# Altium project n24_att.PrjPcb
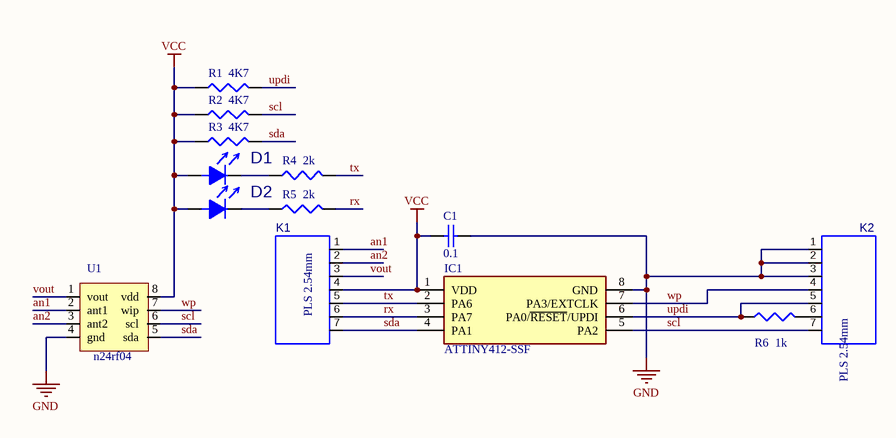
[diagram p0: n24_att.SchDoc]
1 sheet, 13 parts. Net scope: global (net labels, ports and power ports of the same name join across sheets).
Board file: n24_att.PcbDoc

## Sheet n24_att.SchDoc
size A4

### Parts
C1  value 0.1  [SM0805]  (hidden comment: cap0805)
D1  LIGHT_SM0805  [SM0805_diode]  (value not drawn)
D2  LIGHT_SM0805  [SM0805_diode]  (value not drawn)
IC1  ATTINY412-SSF  [SOIC127P600X175-8N]
K1  7_PLS_2.54mm  [7_PLS_2.54]  (value not drawn)
K2  7_PLS_2.54mm  [7_PLS_2.54]  (value not drawn)
R1  value 4K7  [SM0805]  (hidden comment: res0805)
R2  value 4K7  [SM0805]  (hidden comment: res0805)
R3  value 4K7  [SM0805]  (hidden comment: res0805)
R4  value 2k  [SM0805]  (hidden comment: res0805)
R5  value 2k  [SM0805]  (hidden comment: res0805)
R6  value 1k  [SM0805]  (hidden comment: res0805)
U1  n24rf04  [SO8_L]

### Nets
GND: C1.2 IC1.8(GND) K2.1 K2.2 K2.3 U1.4(gnd)
VCC: C1.1 D1.1(a) D2.1(a) IC1.1(VDD) K1.4 R1.1 R2.1 R3.1 U1.8(vdd)
an1: K1.1 U1.2(ant1)
an2: K1.2 U1.3(ant2)
rx: IC1.3(PA7) K1.6 R5.2
scl: IC1.5(PA2) K2.7 R2.2 U1.6(scl)
sda: IC1.4(PA1) K1.7 R3.2 U1.5(sda)
tx: IC1.2(PA6) K1.5 R4.2
updi: IC1.6(PA0/~{RESET}/UPDI) K2.5 R1.2 R6.1
vout: K1.3 U1.1(vout)
wp: IC1.7(PA3/EXTCLK) K2.4 U1.7(wip)
NetD1_2: D1.2(k) R4.1
NetD2_2: D2.2(k) R5.1
NetK2_6: K2.6 R6.2

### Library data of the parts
C1 = cap0805: Capacitor
IC1 = ATTINY412-SSF: Integrated Circuit; Manufacturer_Name: Microchip
K1 K2 = 7_PLS_2.54mm: 7 pin vertical 2.54mm
R1-R6 = res0805: Resistor
U1 = n24rf04: eeprom & nfc tag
